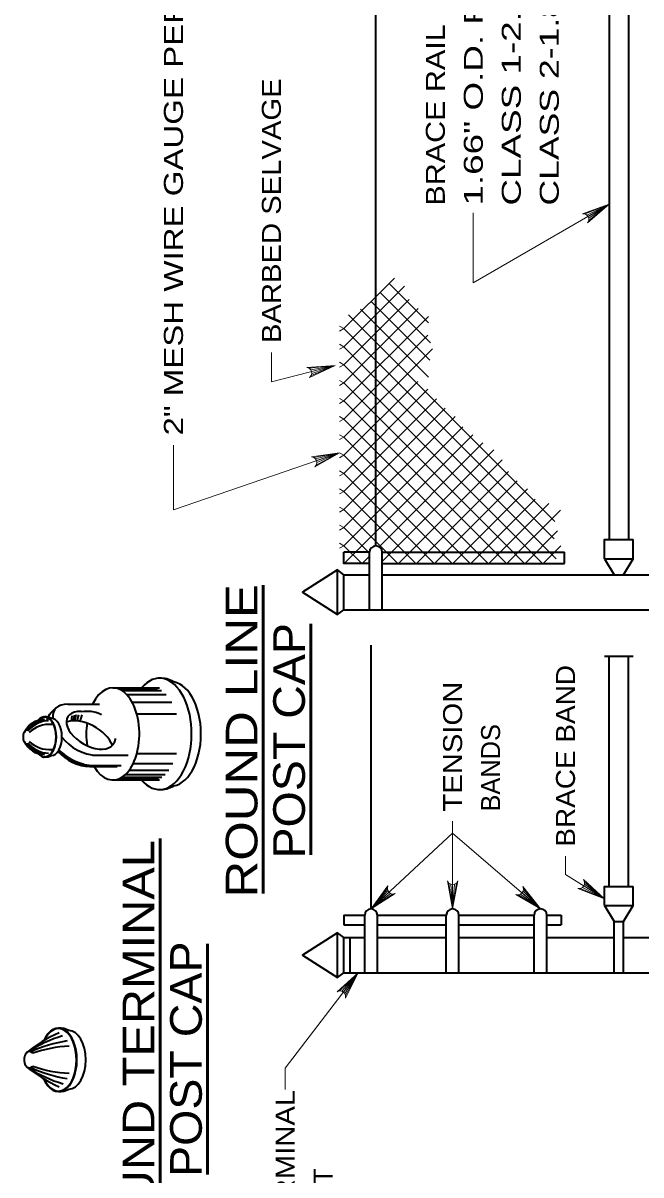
# Model space of a CAD drawing. Extents: x -46.1 to -39.3, y 101.7 to 111.8.
# Drawn here: x -46.074 to -44.121, y 103.496 to 107.135 of the extents above; entities that cross this region are included whole.
import ezdxf
from ezdxf.enums import TextEntityAlignment as Align

# ---------------------------------------------------------------- set-up
doc = ezdxf.new("R2010")
doc.units = 0
doc.header["$LTSCALE"] = 0.024
for name, color, linetype, lineweight in [('1', 7, 'Continuous', 35), ('10', 7, 'Continuous', 13), ('12', 7, 'Continuous', 53), ('6', 7, 'Continuous', 13)]:
    doc.layers.add(name, color=color, linetype=linetype, lineweight=lineweight)

msp = doc.modelspace()

# ---------------------------------------------------------------- linework, layer by layer
at = {"layer": '1'}
for p, q in [((-44.95892, 105.48315), (-44.95892, 111.18012)), ((-44.22154, 108.31144), (-44.22154, 105.50335)), ((-44.16094, 108.31144), (-44.16094, 105.50335)), ((-45.05994, 105.42758), (-45.05994, 105.46294)), ((-44.97912, 105.46294), (-45.05994, 105.46294)), ((-44.97912, 105.28113), (-44.97912, 105.46294)), ((-44.93873, 105.28113), (-44.93873, 105.46294)), ((-44.93873, 105.46294), (-44.36296, 105.46294)), ((-44.36296, 105.42758), (-44.36296, 105.46294)), ((-44.97912, 105.42758), (-45.05994, 105.42758)), ((-44.93873, 105.42758), (-44.36296, 105.42758)), ((-44.23671, 105.44275), (-44.2064, 105.39223)), ((-44.1761, 105.39223), (-44.14579, 105.44275)), ((-45.08015, 105.26598), (-45.08015, 105.4074)), ((-45.05994, 105.28113), (-45.05994, 105.39223)), ((-45.05994, 105.39223), (-44.97912, 105.39223)), ((-44.93873, 105.39223), (-43.22912, 105.39223)), ((-45.05994, 105.28113), (-43.08015, 105.28113)), ((-44.97408, 104.33669), (-44.97408, 105.17)), ((-44.23671, 105.13467), (-44.14579, 105.13467)), ((-44.22154, 104.4074), (-44.22154, 105.13467)), ((-44.16094, 104.4074), (-44.16094, 105.13467)), ((-45.7901, 105.03485), (-45.64258, 105.03485)), ((-45.77477, 105.03242), (-45.64912, 105.03242)), ((-45.76198, 105.02646), (-45.63633, 105.02646)), ((-45.93242, 104.9831), (-45.83269, 104.9831)), ((-45.74671, 105.01396), (-45.62108, 105.01396)), ((-45.72917, 104.98954), (-45.60354, 104.98954)), ((-45.97812, 104.93729), (-45.97975, 104.9431)), ((-45.92063, 104.92823), (-45.91906, 104.9461)), ((-45.9146, 104.92967), (-45.91171, 104.94881)), ((-45.91, 104.93023), (-45.90606, 104.95006)), ((-45.90275, 104.92931), (-45.89742, 104.94977)), ((-45.89371, 104.9286), (-45.887, 104.9494)), ((-45.71444, 104.95262), (-45.58879, 104.95262)), ((-45.85402, 104.8226), (-45.74133, 104.8226)), ((-45.71417, 104.827), (-45.58852, 104.827)), ((-45.86308, 104.788), (-45.77648, 104.788)), ((-45.86308, 104.78604), (-45.77648, 104.78604)), ((-45.85081, 104.78937), (-45.76421, 104.78937)), ((-45.75054, 104.7609), (-45.6249, 104.7609)), ((-45.73837, 104.7746), (-45.61275, 104.7746)), ((-45.7259, 104.79544), (-45.60025, 104.79544)), ((-45.7901, 104.74375), (-45.64258, 104.74375)), ((-45.77194, 104.74721), (-45.64629, 104.74721)), ((-45.76133, 104.75256), (-45.63569, 104.75256)), ((-44.23671, 104.34679), (-44.2064, 104.29627)), ((-44.1761, 104.29627), (-44.14579, 104.34679)), ((-45.05994, 104.31648), (-45.05994, 104.28617)), ((-45.05994, 104.31648), (-44.99427, 104.31648)), ((-44.99427, 104.13467), (-44.99427, 104.31648)), ((-44.95387, 104.13467), (-44.95387, 104.31648)), ((-44.95387, 104.31648), (-44.73671, 104.31648)), ((-44.73671, 104.13467), (-44.73671, 104.31648)), ((-44.69629, 104.13467), (-44.69629, 104.31648)), ((-44.69629, 104.31648), (-44.45892, 104.31648)), ((-44.45892, 104.13467), (-44.45892, 104.31648)), ((-44.41852, 104.13467), (-44.41852, 104.31648)), ((-44.41852, 104.31648), (-44.37306, 104.31648)), ((-44.37306, 104.31648), (-44.37306, 104.28617)), ((-44.2064, 104.13467), (-44.2064, 104.29627)), ((-44.2064, 104.29627), (-44.1761, 104.29627)), ((-44.1761, 104.13467), (-44.1761, 104.29627)), ((-45.08015, 104.1195), (-45.08015, 104.26092)), ((-45.05994, 104.28617), (-44.99427, 104.28617)), ((-44.95387, 104.28617), (-44.73671, 104.28617)), ((-44.69629, 104.28617), (-44.45892, 104.28617)), ((-44.41852, 104.28617), (-44.37306, 104.28617)), ((-45.05994, 104.13467), (-45.05994, 104.24577)), ((-45.05994, 104.24577), (-44.99427, 104.24577)), ((-45.03973, 104.13467), (-45.03973, 104.24577)), ((-44.95387, 104.24577), (-44.73671, 104.24577)), ((-44.69629, 104.24577), (-44.45892, 104.24577)), ((-44.41852, 104.24577), (-44.2064, 104.24577)), ((-44.1761, 104.24577), (-43.98671, 104.24577)), ((-45.05994, 104.13467), (-43.08015, 104.13467))]:
    msp.add_line(p, q, dxfattribs=at)
for points in [[(-44.23671, 105.44275), (-44.14579, 105.44275), (-44.14579, 105.50335)], [(-44.23671, 105.44275), (-44.23671, 105.50335), (-44.14579, 105.50335)], [(-45.05994, 105.39223), (-45.08015, 105.4074), (-45.19125, 105.33669), (-45.08015, 105.26598), (-45.05994, 105.28113)], [(-44.23671, 104.34679), (-44.14579, 104.34679), (-44.14579, 104.4074)], [(-44.23671, 104.34679), (-44.23671, 104.4074), (-44.14579, 104.4074)], [(-45.05994, 104.24577), (-45.08015, 104.26092), (-45.19125, 104.19021), (-45.08015, 104.1195), (-45.05994, 104.13467)]]:
    msp.add_lwpolyline(points, dxfattribs=at)
for centre, radius, start, end in [((-44.95893, 105.46294), 0.0202, 0, 180), ((-45.64012, 104.98257), 0.08264, 59.99787, 91.71298), ((-46.00407, 104.90211), 0.04102, 61.82978, 92.05261), ((-46.00436, 104.8619), 0.07337, 90.91486, 154.43259), ((-45.98039, 104.83224), 0.10604, 103.71895, 140.75253), ((-45.99065, 104.84589), 0.08518, 91.74487, 142.42163), ((-45.99055, 104.82705), 0.09224, 85.19311, 133.85653), ((-46.00436, 104.89737), 0.07337, 205.56741, 269.08514), ((-45.98039, 104.92702), 0.10604, 219.24748, 256.28105), ((-45.99065, 104.91337), 0.08518, 217.57837, 268.25513), ((-45.99055, 104.93221), 0.09224, 226.14347, 274.80689), ((-46.00407, 104.85715), 0.04102, 267.94739, 298.17022), ((-45.64012, 104.79604), 0.08264, 268.28702, 300.00213), ((-44.97408, 104.31648), 0.0202, 0, 180), ((-44.7165, 104.31648), 0.0202, 0, 180), ((-44.43872, 104.31648), 0.0202, 0, 180), ((-45.95965, 103.89518), 0.06473, 61.82978, 92.05261), ((-45.95965, 103.82424), 0.06473, 267.94739, 298.17022)]:
    msp.add_arc(centre, radius, start, end, dxfattribs=at)
for centre, major_axis, ratio, start_param, end_param in [((-45.64259, 104.88931), (0, 0.17587), 0.57735, 2.5382808, 6.87919), ((-45.60686, 104.88924), (0, 0.16484), 0.57735, 3.1415927, 6.2831853), ((-45.79011, 104.88931), (0, 0.14555), 0.57735, 2.3596135, 7.151429), ((-45.8945, 104.91706), (-0.08089, 0.0467), 0.57735, 5.4977855, 6.6966228), ((-46.00553, 104.87963), (0, 0.06347), 0.583246, 2.5358265, 6.8889678), ((-46.00553, 104.87963), (0, 0.06306), 0.580503, 2.5518233, 6.8731951), ((-46.00553, 104.87963), (0, 0.06259), 0.57735, 2.5704403, 6.8543494), ((-45.86008, 104.9006), (-0.07278, 0.04202), 0.57735, 5.4445167, 9.3331797), ((-45.9847, 104.87963), (0, 0.05864), 0.57735, 3.1415927, 6.2831853), ((-45.87353, 104.8648), (-0.08089, 0.0467), 0.57735, 3.7457427, 5.8228226), ((-45.79011, 104.88931), (0, 0.14555), 0.57735, 1.3268571, 1.8271935), ((-46.06251, 104.87963), (0, 0.0197), 0.57735, 0.7853646, 2.356228), ((-45.88028, 104.88789), (-0.08089, 0.0467), 0.57735, 0.9177763, 2.3561928), ((-45.90122, 104.85208), (-0.08089, 0.0467), 0.57735, 1.0629081, 2.3561928), ((-45.90122, 104.85208), (-0.07918, 0.04572), 0.568245, 1.0474957, 2.4105232), ((-45.90122, 104.85208), (-0.07748, 0.04473), 0.55874, 1.0303055, 2.4018209), ((-45.89412, 104.86438), (-0.09185, 0.05303), 0.57735, 1.1178918, 2.3563082), ((-45.90122, 104.85208), (-0.07577, 0.04375), 0.548806, 1.046674, 2.094496), ((-45.96197, 103.85971), (0, 0.10016), 0.583246, 2.211658, 7.2023458), ((-45.96197, 103.85971), (0, 0.0995), 0.580503, 2.2235808, 7.1901726), ((-45.96197, 103.85971), (0, 0.09876), 0.57735, 2.2375049, 7.1759449), ((-45.9121, 103.77965), (-0.23442, -0.12488), 0.639967, 4.5770202, 5.0362937), ((-45.91688, 103.76689), (-0.24872, -0.09322), 0.639967, 4.6048477, 5.0545363), ((-45.92909, 103.85971), (0, 0.09253), 0.57735, 3.1415927, 6.2831853), ((-46.0536, 103.86003), (0, 0.02592), 0.655085, 5.6232559, 10.0847074), ((-45.93, 103.7472), (-0.25829, -0.06193), 0.639967, 4.5770202, 5.0315753), ((-45.94079, 103.73121), (-0.26313, -0.03619), 0.639967, 4.5770202, 5.02273), ((-45.9121, 103.94041), (-0.23442, 0.12488), 0.639967, 1.2468916, 1.7061651), ((-45.91688, 103.95317), (-0.24872, 0.09322), 0.639967, 1.228649, 1.6871745), ((-45.93, 103.97286), (-0.25829, 0.06193), 0.639967, 1.25161, 1.7061651), ((-45.94079, 103.98885), (-0.26313, 0.03619), 0.639967, 1.2604554, 1.7061651)]:
    msp.add_ellipse(centre, major_axis=major_axis, ratio=ratio, start_param=start_param, end_param=end_param, dxfattribs=at)
for points in [[(-45.99702, 104.92956), (-45.99704, 104.9314), (-45.9731, 104.96879)], [(-45.89069, 104.95994), (-45.84962, 104.95906), (-45.82644, 104.95083)], [(-45.78983, 104.85492), (-45.78379, 104.86483), (-45.78154, 104.87456)]]:
    msp.add_spline(points, degree=3, dxfattribs=at)
at = {"layer": '10'}
for p, q in [((-45.2891, 106.09373), (-45.2891, 106.00137)), ((-45.2891, 106.00137), (-45.08765, 106.05283)), ((-45.59856, 105.80163), (-45.59856, 105.5974)), ((-45.59856, 105.5974), (-45.07356, 105.77731)), ((-44.7165, 104.33669), (-44.7165, 104.61371)), ((-44.7165, 104.57581), (-44.97408, 104.33669)), ((-44.7165, 104.57581), (-44.43873, 104.33669)), ((-44.35977, 104.44463), (-44.35977, 104.50281)), ((-44.23671, 104.36827), (-44.35977, 104.44463)), ((-45.01485, 104.13467), (-45.24546, 103.83292)), ((-45.24546, 103.83292), (-45.24546, 103.76596))]:
    msp.add_line(p, q, dxfattribs=at)
for points in [[(-44.6516, 106.53552), (-44.6516, 106.31398), (-44.22154, 106.56223)], [(-44.22154, 106.56223), (-44.28973, 106.50377), (-44.28619, 106.51125), (-44.2861, 106.51812), (-44.28819, 106.52375), (-44.29202, 106.52837), (-44.29802, 106.53175), (-44.30627, 106.53244), (-44.22154, 106.56223), (-44.29802, 106.53175), (-44.29202, 106.52837), (-44.22154, 106.56223), (-44.28819, 106.52375), (-44.2861, 106.51812), (-44.22154, 106.56223), (-44.28619, 106.51125)], [(-45.08765, 106.05283), (-45.16906, 106.01496), (-45.16365, 106.02121), (-45.16171, 106.02781), (-45.16221, 106.03379), (-45.16465, 106.03927), (-45.1695, 106.04415), (-45.17727, 106.04702), (-45.08765, 106.05283), (-45.1695, 106.04415), (-45.16465, 106.03927), (-45.08765, 106.05283), (-45.16221, 106.03379), (-45.16171, 106.02781), (-45.08765, 106.05283), (-45.16365, 106.02121)], [(-45.07356, 105.77731), (-45.15169, 105.73304), (-45.14679, 105.73971), (-45.1454, 105.74644), (-45.14635, 105.75238), (-45.14923, 105.75765), (-45.15446, 105.7621), (-45.16244, 105.76435), (-45.07356, 105.77731), (-45.15446, 105.7621), (-45.14923, 105.75765), (-45.07356, 105.77731), (-45.14635, 105.75238), (-45.1454, 105.74644), (-45.07356, 105.77731), (-45.14679, 105.73971)], [(-44.97408, 104.33669), (-44.92065, 104.40885), (-44.92244, 104.40079), (-44.92098, 104.39406), (-44.91769, 104.38902), (-44.91292, 104.38537), (-44.90631, 104.38344), (-44.89813, 104.3846), (-44.97408, 104.33669), (-44.90631, 104.38344), (-44.91292, 104.38537), (-44.97408, 104.33669), (-44.91769, 104.38902), (-44.92098, 104.39406), (-44.97408, 104.33669), (-44.92244, 104.40079)], [(-44.7165, 104.33669), (-44.73304, 104.42494), (-44.72833, 104.41815), (-44.72242, 104.41465), (-44.7165, 104.41362), (-44.71058, 104.41465), (-44.70467, 104.41815), (-44.69996, 104.42494), (-44.7165, 104.33669), (-44.70467, 104.41815), (-44.71058, 104.41465), (-44.7165, 104.33669), (-44.7165, 104.41362), (-44.72242, 104.41465), (-44.7165, 104.33669), (-44.72833, 104.41815)], [(-44.43873, 104.33669), (-44.51642, 104.38173), (-44.50819, 104.38085), (-44.50167, 104.38306), (-44.49704, 104.38688), (-44.49394, 104.39202), (-44.49273, 104.39879), (-44.49481, 104.40681), (-44.43873, 104.33669), (-44.49273, 104.39879), (-44.49394, 104.39202), (-44.43873, 104.33669), (-44.49704, 104.38688), (-44.50167, 104.38306), (-44.43873, 104.33669), (-44.50819, 104.38085)], [(-44.23671, 104.36827), (-44.32044, 104.40071), (-44.31219, 104.40115), (-44.30608, 104.40431), (-44.3021, 104.40881), (-44.29983, 104.41437), (-44.29971, 104.42125), (-44.303, 104.42885), (-44.23671, 104.36827), (-44.29971, 104.42125), (-44.29983, 104.41437), (-44.23671, 104.36827), (-44.3021, 104.40881), (-44.30608, 104.40431), (-44.23671, 104.36827), (-44.31219, 104.40115)], [(-45.01485, 104.13467), (-45.05529, 104.05448), (-45.0549, 104.06275), (-45.05748, 104.06912), (-45.06156, 104.07352), (-45.06687, 104.07631), (-45.07371, 104.07712), (-45.08158, 104.07458), (-45.01485, 104.13467), (-45.07371, 104.07712), (-45.06687, 104.07631), (-45.01485, 104.13467), (-45.06156, 104.07352), (-45.05748, 104.06912), (-45.01485, 104.13467), (-45.0549, 104.06275)]]:
    msp.add_lwpolyline(points, dxfattribs=at)
at = {"layer": '12'}
for p, q in [((-45.31467, 105.35927), (-45.31467, 104.3855)), ((-45.16467, 104.50735), (-45.16467, 105.23744)), ((-45.64046, 103.17296), (-45.64046, 104.55846)), ((-45.49046, 103.49706), (-45.49046, 104.22617))]:
    msp.add_line(p, q, dxfattribs=at)
at = {"layer": '6'}
for p, q in [((-45.05994, 106.16944), (-44.90052, 106.32883)), ((-45.05994, 106.11229), (-44.86821, 106.304)), ((-44.91708, 106.31227), (-44.79298, 106.18819)), ((-45.05994, 106.05515), (-44.8534, 106.26169)), ((-44.97423, 106.25515), (-44.7889, 106.06979)), ((-44.94565, 106.28371), (-44.78656, 106.12462)), ((-45.05994, 105.998), (-44.82483, 106.2331)), ((-45.00735, 106.23112), (-44.79246, 106.01623)), ((-45.05994, 105.94087), (-44.79252, 106.20827)), ((-45.04592, 106.21254), (-44.39373, 105.56035)), ((-45.05994, 106.16944), (-44.39604, 105.50554)), ((-45.05994, 105.88373), (-44.79519, 106.14846)), ((-45.05994, 106.11229), (-44.38962, 105.44198)), ((-45.05994, 105.82658), (-44.78037, 106.10615)), ((-45.05994, 106.05515), (-44.43238, 105.42758)), ((-45.05994, 105.76946), (-44.82677, 106.0026)), ((-45.05994, 105.998), (-44.48952, 105.42758)), ((-45.05994, 105.71231), (-44.79448, 105.97777)), ((-45.05994, 105.65517), (-44.76717, 105.94794)), ((-45.05994, 105.94087), (-44.54665, 105.42758)), ((-45.05994, 105.59802), (-44.73985, 105.91813)), ((-45.05994, 105.5409), (-44.70879, 105.89204)), ((-45.05994, 105.88373), (-44.60379, 105.42758)), ((-45.05994, 105.48375), (-44.68398, 105.85971)), ((-45.05994, 105.82658), (-44.66094, 105.42758)), ((-45.05896, 105.42758), (-44.65292, 105.83362)), ((-44.94892, 105.4805), (-44.6206, 105.80881)), ((-44.93873, 105.43354), (-44.58579, 105.78648)), ((-45.05994, 105.76946), (-44.71808, 105.42758)), ((-44.88754, 105.42758), (-44.55973, 105.7554)), ((-45.05994, 105.71231), (-44.77521, 105.42758)), ((-44.8304, 105.42758), (-44.53992, 105.71806)), ((-44.77325, 105.42758), (-44.5126, 105.68825)), ((-45.05994, 105.65517), (-44.83235, 105.42758)), ((-44.7161, 105.42758), (-44.48029, 105.66342)), ((-45.05994, 105.59802), (-44.8895, 105.42758)), ((-44.65898, 105.42758), (-44.45548, 105.63108)), ((-44.60183, 105.42758), (-44.41192, 105.6175)), ((-44.54469, 105.42758), (-44.37585, 105.59642)), ((-45.05994, 105.5409), (-44.97912, 105.46008)), ((-44.48756, 105.42758), (-44.38479, 105.53035)), ((-45.05994, 105.48375), (-45.00377, 105.42758)), ((-44.43042, 105.42758), (-44.37496, 105.48304)), ((-45.05994, 105.4266), (-45.06092, 105.42758)), ((-45.00279, 105.4266), (-44.97912, 105.45027))]:
    msp.add_line(p, q, dxfattribs=at)
for points in [[(-45.07356, 106.16156), (-45.05994, 106.16944), (-45.07356, 106.17729)], [(-45.07356, 106.10442), (-45.05994, 106.11229), (-45.07356, 106.12017)], [(-45.07356, 106.04727), (-45.05994, 106.05515), (-45.07356, 106.06302)], [(-45.07356, 105.99015), (-45.05994, 105.998), (-45.07356, 106.00588)], [(-45.07356, 105.933), (-45.05994, 105.94087), (-45.07356, 105.94873)], [(-45.07356, 105.87585), (-45.05994, 105.88373), (-45.07356, 105.8916)], [(-45.07356, 105.81871), (-45.05994, 105.82658), (-45.07356, 105.83446)], [(-45.07356, 105.76158), (-45.05994, 105.76946), (-45.07356, 105.77731)], [(-45.07356, 105.70444), (-45.05994, 105.71231), (-45.07356, 105.72019)], [(-45.07356, 105.64729), (-45.05994, 105.65517), (-45.07356, 105.66304)], [(-45.07356, 105.59017), (-45.05994, 105.59802), (-45.07356, 105.6059)], [(-45.07356, 105.53302), (-45.05994, 105.5409), (-45.07356, 105.54875)], [(-45.07356, 105.47588), (-45.05994, 105.48375), (-45.07356, 105.49162)]]:
    msp.add_lwpolyline(points, dxfattribs=at)

# ---------------------------------------------------------------- texts
at = {"layer": '12'}
for s, width, p in [('2" MESH WIRE GAUGE PER SPECIFICATIONS CHAIN LINK FENCE', 1.3, (-45.56855, 105.83191)), ('CLASS 1-2.27 #/FT. OR', 1.45, (-44.50099, 106.55823)), ('CLASS 2-1.84 #/FT.', 1.4, (-44.38099, 106.55823)), ('1.66" O.D. PIPE', 1.45, (-44.62099, 106.55823)), ('BRACE RAIL', 1.2, (-44.74099, 106.55823)), ('BARBED SELVAGE', 1.15, (-45.25909, 106.12402)), ('BRACE BAND', 1.1, (-44.32976, 104.5331)), ('TENSION', 1.15, (-44.68649, 104.64399)), ('TERMINAL', 1.15, (-45.21546, 103.29828))]:
    msp.add_text(s, height=0.06, rotation=90, dxfattribs=dict(at, width=width)).set_placement(p)
for s, width, p in [('ROUND LINE', 1.2, (-45.33325, 104.86756)), ('POST CAP', 1.1, (-45.18325, 104.86755)), ('ROUND TERMINAL', 1.15, (-45.65904, 103.8616)), ('POST CAP', 1.1, (-45.50904, 103.8616))]:
    msp.add_text(s, height=0.1, rotation=90, dxfattribs=dict(at, width=width)).set_placement(p, align=Align.CENTER)
for s, p in [('BANDS', (-44.56649, 104.64399)), ('POST', (-45.09546, 103.29828))]:
    msp.add_text(s, height=0.06, rotation=90, dxfattribs=at).set_placement(p)

doc.saveas('drawing.dxf')
